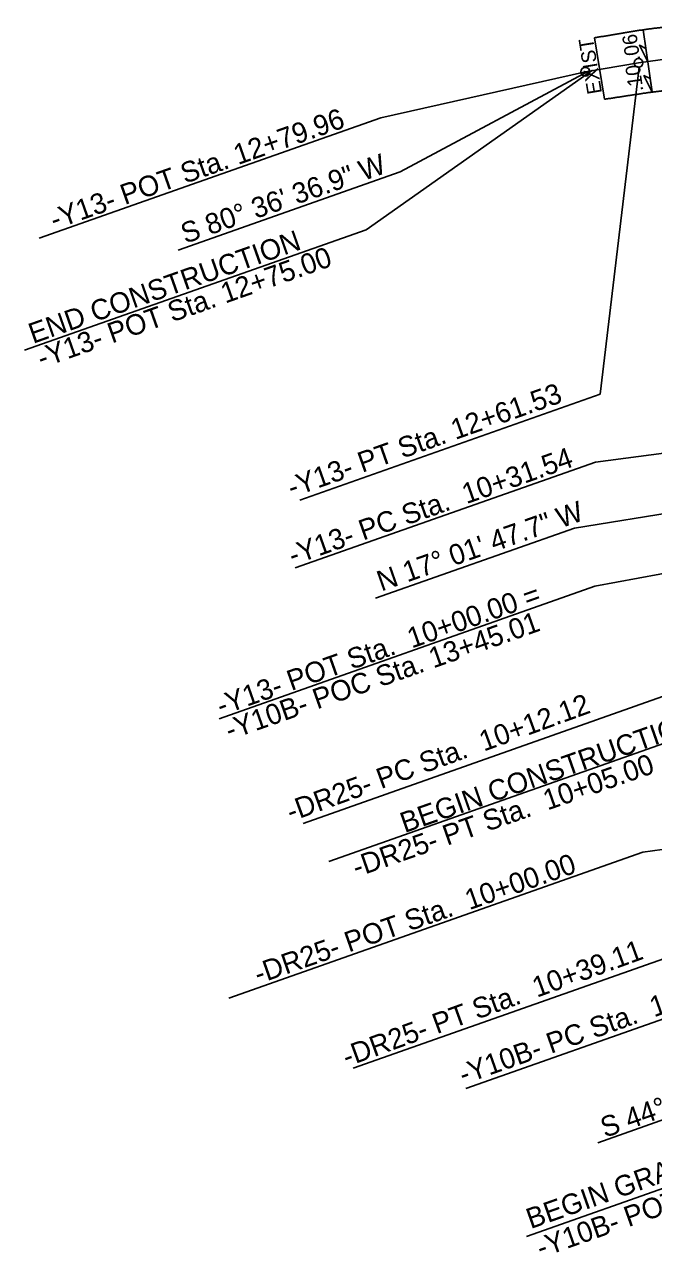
# Model space of a CAD drawing. Extents: x 472216 to 481979, y 489069 to 507339.
# Drawn here: x 474882.1 to 475097.2, y 501791.3 to 502211.4 of the extents above; entities that cross this region are included whole.
import ezdxf

# ---------------------------------------------------------------- set-up
doc = ezdxf.new("R2010")
doc.units = 0
for name, color, linetype in [('Old_Level_12', 7, 'Continuous'), ('Prop Drainage Structure Drop Inlet Grate 2 Narrow Slots and Sag Grates 840 24 CELL', 7, 'Continuous'), ('Prop Drainage Structure Drop Inlet Grate 2 Wide Slots and Sag Grates 840 22 Label', 7, 'Continuous'), ('Prop Drainage Structure Pipe RCP 24in Class III Label', 7, 'Continuous'), ('Sheet North Arrow Point CELL', 7, 'Continuous'), ('Sheet Plan And Profile CELL', 7, 'Continuous')]:
    doc.layers.add(name, color=color, linetype=linetype)

msp = doc.modelspace()

# ---------------------------------------------------------------- linework, layer by layer
at = {"layer": 'Old_Level_12'}
for p, q in [((475076.42, 502195.73), (474998.96, 502141.12)), ((475073.94, 502195.22), (475003.99, 502179.49)), ((475074.98, 502195.39), (475010.53, 502160.94)), ((475092.37, 502196.74), (475078.96, 502084.87)), ((475003.99, 502179.49), (474887.11, 502138.28)), ((475010.53, 502160.94), (474934.6, 502134.17)), ((474998.96, 502141.12), (474882.08, 502099.91)), ((475269.77, 502086.79), (475077.41, 502061.69)), ((475078.96, 502084.87), (474976.21, 502048.64)), ((475070.19, 502039.1), (475275.83, 502072.15)), ((475077.41, 502061.69), (474974.67, 502025.46)), ((475279.01, 502056.63), (475077.17, 502019.19)), ((475070.19, 502039.1), (475002.13, 502015.1)), ((475077.17, 502019.19), (474948.69, 501973.88)), ((475106.2, 501983.48), (474977.38, 501938.06)), ((475113.99, 501970.13), (474986.13, 501925.05)), ((475156.61, 501937.24), (475093.66, 501928.19)), ((475093.66, 501928.19), (474952.02, 501878.25)), ((475106.98, 501894), (474994.46, 501854.33)), ((475149.97, 501888.63), (475033.09, 501847.41)), ((475152.41, 501854.98), (475078.23, 501828.82)), ((475177.25, 501840.27), (475053.77, 501796.73))]:
    msp.add_line(p, q, dxfattribs=at)
for centre in [(475092.12, 502198.22), (475073.94, 502195.22)]:
    msp.add_circle(centre, 1.5, dxfattribs=at)
at = {"layer": 'Prop Drainage Structure Drop Inlet Grate 2 Narrow Slots and Sag Grates 840 24 CELL'}
for points in [[(475095.3, 502198.64), (475092.46, 502204.29), (475094.63, 502203.22)], [(475096.8, 502188.27), (475093.96, 502193.92), (475096.13, 502192.85)]]:
    msp.add_lwpolyline(points, close=True, dxfattribs=at)
at = {"layer": 'Prop Drainage Structure Drop Inlet Grate 2 Wide Slots and Sag Grates 840 22 Label'}
msp.add_line((475093.71, 502209.56), (475096.79, 502188.34), dxfattribs=at)
at = {"layer": 'Prop Drainage Structure Pipe RCP 24in Class III Label'}
msp.add_line((475080.52, 502185.81), (475077.05, 502206.82), dxfattribs=at)
for points in [[(475129.24, 502211.01), (475128.52, 502211.06), (475127.79, 502211.1), (475127.07, 502211.14), (475126.35, 502211.17), (475125.63, 502211.2), (475124.91, 502211.23), (475124.19, 502211.26), (475123.47, 502211.28), (475122.74, 502211.3), (475122.02, 502211.32), (475121.3, 502211.33), (475120.58, 502211.34), (475119.86, 502211.35), (475119.13, 502211.35), (475118.41, 502211.36), (475117.69, 502211.35), (475116.97, 502211.35), (475116.25, 502211.34), (475115.52, 502211.33), (475114.8, 502211.32), (475114.08, 502211.3), (475113.36, 502211.28), (475112.64, 502211.26), (475111.92, 502211.23), (475111.19, 502211.2), (475110.47, 502211.17), (475109.75, 502211.14), (475109.03, 502211.1), (475108.31, 502211.06), (475107.59, 502211.01), (475106.87, 502210.97), (475106.15, 502210.92), (475105.43, 502210.86), (475104.71, 502210.81), (475103.99, 502210.75), (475103.27, 502210.69), (475102.55, 502210.62), (475101.83, 502210.55), (475101.11, 502210.48), (475100.39, 502210.41), (475099.68, 502210.33), (475098.96, 502210.25), (475098.24, 502210.16), (475097.53, 502210.08), (475096.81, 502209.99), (475096.09, 502209.89), (475095.38, 502209.8), (475094.66, 502209.7), (475093.95, 502209.6), (475093.23, 502209.49), (475092.52, 502209.39), (475091.81, 502209.28), (475091.09, 502209.16), (475090.38, 502209.04), (475089.71, 502208.93), (475089.04, 502208.82), (475088.38, 502208.71), (475087.71, 502208.6), (475087.04, 502208.49), (475086.38, 502208.38), (475085.71, 502208.27), (475085.05, 502208.16), (475084.38, 502208.05), (475083.71, 502207.93), (475083.05, 502207.82), (475082.38, 502207.71), (475081.71, 502207.6), (475081.05, 502207.49), (475080.38, 502207.38), (475079.71, 502207.27), (475079.05, 502207.16), (475078.38, 502207.05), (475077.05, 502206.82)], [(475127.82, 502189.06), (475127.19, 502189.11), (475126.56, 502189.15), (475125.94, 502189.19), (475125.31, 502189.23), (475124.68, 502189.27), (475124.05, 502189.31), (475123.42, 502189.34), (475122.79, 502189.37), (475122.17, 502189.39), (475121.54, 502189.42), (475120.91, 502189.44), (475120.28, 502189.46), (475119.65, 502189.47), (475119.02, 502189.49), (475118.39, 502189.5), (475117.76, 502189.51), (475117.13, 502189.51), (475116.5, 502189.51), (475115.87, 502189.51), (475115.24, 502189.51), (475114.61, 502189.51), (475113.98, 502189.5), (475113.35, 502189.49), (475112.72, 502189.47), (475112.09, 502189.46), (475111.46, 502189.44), (475110.83, 502189.42), (475110.2, 502189.39), (475109.57, 502189.37), (475108.94, 502189.34), (475108.31, 502189.31), (475107.68, 502189.27), (475107.05, 502189.23), (475106.42, 502189.19), (475105.79, 502189.15), (475105.16, 502189.11), (475104.54, 502189.06), (475103.91, 502189.01), (475103.28, 502188.96), (475102.65, 502188.9), (475102.02, 502188.84), (475101.39, 502188.78), (475100.77, 502188.72), (475100.14, 502188.65), (475099.51, 502188.58), (475098.88, 502188.51), (475098.26, 502188.43), (475097.63, 502188.36), (475097.01, 502188.28), (475096.38, 502188.2), (475095.75, 502188.11), (475095.13, 502188.02), (475094.51, 502187.93), (475093.88, 502187.84), (475093.22, 502187.74), (475092.55, 502187.64), (475091.88, 502187.53), (475091.21, 502187.43), (475090.54, 502187.33), (475089.88, 502187.23), (475089.21, 502187.13), (475088.54, 502187.03), (475087.87, 502186.92), (475087.2, 502186.82), (475086.54, 502186.72), (475085.87, 502186.62), (475085.2, 502186.52), (475084.53, 502186.42), (475083.86, 502186.31), (475083.2, 502186.21), (475082.53, 502186.11), (475081.86, 502186.01), (475080.52, 502185.81)]]:
    msp.add_spline(points, degree=3, dxfattribs=at)
at = {"layer": 'Sheet North Arrow Point CELL'}
msp.add_line((475092.12, 502198.22), (475073.94, 502195.22), dxfattribs=at)
msp.add_arc((475118.22, 502040.37), 160, 17.0299, 99.3898, dxfattribs=at)

# ---------------------------------------------------------------- texts
at = {"layer": 'Old_Level_12'}
for s, rotation, p in [('-Y13- POT Sta. 12+79.96', 19.423, (474892.31, 502141.12)), ('END CONSTRUCTION', 19.423, (474884.98, 502102.09)), ('-Y13- POT Sta. 12+75.00', 19.423, (474887.93, 502093.72)), ('-Y13- PT Sta. 12+61.53', 19.423, (474973.53, 502049.51)), ('-Y13- PC Sta.  10+31.54', 19.423, (474973.87, 502026.31)), ('-Y13- POT Sta.  10+00.00 = ', 19.423, (474949.29, 501974.85)), ('-Y10B- POC Sta. 13+45.01', 19.423, (474952.24, 501966.48)), ('-DR25- PC Sta.  10+12.12', 20.0064, (474973.23, 501938.57)), ('BEGIN CONSTRUCTION', 19.3241, (475012.11, 501934.72)), ('-DR25- PT Sta.  10+05.00', 19.3241, (474995.7, 501919.56)), ('-DR25- POT Sta.  10+00.00', 19.3241, (474962.1, 501883.04)), ('-DR25- PT Sta.  10+39.11', 20.0309, (474992.36, 501854.7)), ('-Y10B- PC Sta.  12+59.33', 19.423, (475032.19, 501848.67)), ('-Y10B- POT Sta. 11+86.00', 19.423, (475058.73, 501789.34)), ('BEGIN GRADE', 19.423, (475055.24, 501799.24))]:
    msp.add_text(s, height=7, rotation=rotation, dxfattribs=at).set_placement(p)
at = {"layer": 'Prop Drainage Structure Drop Inlet Grate 2 Narrow Slots and Sag Grates 840 24 CELL'}
for s, rotation, p in [('.06', 98.2432, (475092.75, 502199.21)), ('EXIST', 99.3898, (475079.66, 502187.97)), ('.10', 98.2432, (475093.82, 502188.7))]:
    msp.add_text(s, height=5, rotation=rotation, dxfattribs=at).set_placement(p)
at = {"layer": 'Sheet Plan And Profile CELL'}
for s, p in [('S 80%%d 36\' 36.9" W', (474937.06, 502136.33)), ('N 17%%d 01\' 47.7" W', (475004.15, 502017.36)), ('S 44%%d 34\' 26.2" E', (475080.64, 501830.44))]:
    msp.add_text(s, height=7, rotation=19.423, dxfattribs=at).set_placement(p)

doc.saveas('drawing.dxf')
